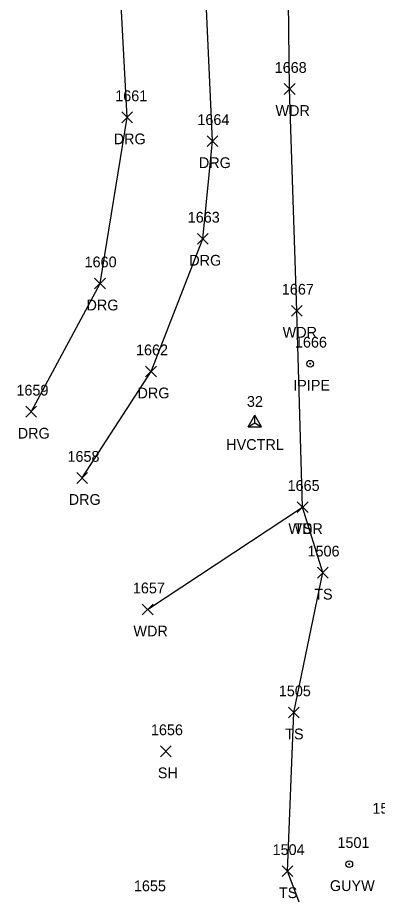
# Model space of a CAD drawing. Extents: x 1551995 to 1555700, y 777276 to 783130.
# Drawn here: x 1554729.2 to 1554796.1, y 777646.9 to 777809.8 of the extents above; entities that cross this region are included whole.
import ezdxf

# ---------------------------------------------------------------- set-up
doc = ezdxf.new("R2010")
doc.units = 0
for name, color, linetype in [('C_A', 7, 'Continuous'), ('C_I', 7, 'Continuous'), ('CPSM', 7, 'Continuous'), ('L_A', 7, 'Continuous'), ('L_I', 7, 'Continuous'), ('L_TIC', 7, 'Continuous'), ('LAWA', 7, 'Continuous'), ('LELB', 7, 'Continuous'), ('M_A', 7, 'Continuous'), ('M_I', 7, 'Continuous'), ('MPIP', 7, 'Continuous'), ('R_A', 7, 'Continuous'), ('R_I', 7, 'Continuous'), ('R_TIC', 7, 'Continuous'), ('RDG', 7, 'Continuous'), ('U_A', 7, 'Continuous'), ('U_I', 7, 'Continuous'), ('UPGW', 7, 'Continuous')]:
    doc.layers.add(name, color=color, linetype=linetype)

msp = doc.modelspace()

# ---------------------------------------------------------------- linework, layer by layer
at = {"layer": 'CPSM'}
for p, q in [((1554772.03, 777733.75), (1554773.28, 777735.92)), ((1554774.53, 777733.75), (1554773.28, 777735.92)), ((1554773.28, 777734.47), (1554773.28, 777735.92)), ((1554772.03, 777733.75), (1554773.28, 777734.47)), ((1554773.28, 777734.47), (1554773.28, 777734.47)), ((1554773.28, 777734.47), (1554774.53, 777733.75)), ((1554772.03, 777733.75), (1554774.53, 777733.75))]:
    msp.add_line(p, q, dxfattribs=at)
at = {"layer": 'L_TIC'}
for points in [[(1554778.76, 777795.52), (1554780.76, 777797.52)], [(1554780.76, 777795.52), (1554778.76, 777797.52)], [(1554780.09, 777754.32), (1554782.09, 777756.32)], [(1554782.09, 777754.32), (1554780.09, 777756.32)], [(1554781.17, 777717.85), (1554783.17, 777719.85)], [(1554783.17, 777717.85), (1554781.17, 777719.85)], [(1554781.17, 777717.85), (1554783.17, 777719.85)], [(1554783.17, 777717.85), (1554781.17, 777719.85)], [(1554784.91, 777705.67), (1554786.91, 777707.67)], [(1554786.91, 777705.67), (1554784.91, 777707.67)], [(1554752.38, 777698.82), (1554754.38, 777700.82)], [(1554754.38, 777698.82), (1554752.38, 777700.82)], [(1554779.53, 777679.7), (1554781.53, 777681.7)], [(1554781.53, 777679.7), (1554779.53, 777681.7)], [(1554755.78, 777672.47), (1554757.78, 777674.47)], [(1554757.78, 777672.47), (1554755.78, 777674.47)], [(1554778.36, 777650.21), (1554780.36, 777652.21)], [(1554780.36, 777650.21), (1554778.36, 777652.21)]]:
    msp.add_lwpolyline(points, dxfattribs=at)
at = {"layer": 'LAWA'}
msp.add_lwpolyline([(1554753.38, 777699.82), (1554782.17, 777718.85), (1554781.09, 777755.32), (1554779.76, 777796.52), (1554779.3, 777834.65), (1554766.43, 777889.19), (1554764.95, 777942.26), (1554753, 777988.87), (1554759.44, 778026.67), (1554773.64, 778068.32), (1554781.91, 778071.15), (1554798.07, 778075.08), (1554813.64, 778080.72)], dxfattribs=at)
at = {"layer": 'LELB'}
msp.add_lwpolyline([(1554784.41, 777637.79), (1554779.36, 777651.21), (1554780.53, 777680.7), (1554785.91, 777706.67), (1554782.17, 777718.85)], dxfattribs=at)
at = {"layer": 'MPIP'}
for radius in [0.625, 0.0833]:
    msp.add_circle((1554783.58, 777745.48), radius, dxfattribs=at)
at = {"layer": 'R_TIC'}
for points in [[(1554748.58, 777790.25), (1554750.58, 777792.25)], [(1554750.58, 777790.25), (1554748.58, 777792.25)], [(1554764.41, 777785.83), (1554766.41, 777787.83)], [(1554766.41, 777785.83), (1554764.41, 777787.83)], [(1554762.62, 777767.7), (1554764.62, 777769.7)], [(1554764.62, 777767.7), (1554762.62, 777769.7)], [(1554743.54, 777759.39), (1554745.54, 777761.39)], [(1554745.54, 777759.39), (1554743.54, 777761.39)], [(1554753.01, 777743.05), (1554755.01, 777745.05)], [(1554755.01, 777743.05), (1554753.01, 777745.05)], [(1554730.76, 777735.57), (1554732.76, 777737.57)], [(1554732.76, 777735.57), (1554730.76, 777737.57)], [(1554740.23, 777723.26), (1554742.23, 777725.26)], [(1554742.23, 777723.26), (1554740.23, 777725.26)]]:
    msp.add_lwpolyline(points, dxfattribs=at)
at = {"layer": 'RDG'}
for points in [[(1554731.76, 777736.57), (1554744.54, 777760.39), (1554749.58, 777791.25), (1554744.63, 777884.27), (1554742.18, 777937.77), (1554733.78, 777989.36), (1554731.62, 778029.74), (1554732.87, 778072.64), (1554738.87, 778112.72), (1554741.1, 778122.89), (1554752.14, 778165.58), (1554757.04, 778182.47), (1554765.14, 778213.69), (1554774.89, 778246.18), (1554785.77, 778269.3), (1554800.7, 778290.2), (1554833.81, 778326.22), (1554863.94, 778353.44), (1554894.55, 778381.82), (1554916.32, 778408.8)], [(1554741.23, 777724.26), (1554754.01, 777744.05), (1554763.62, 777768.7), (1554765.41, 777786.83), (1554760.87, 777887.93)]]:
    msp.add_lwpolyline(points, dxfattribs=at)
at = {"layer": 'UPGW'}
for radius in [0.625, 0.0833]:
    msp.add_circle((1554790.84, 777652.52), radius, dxfattribs=at)

# ---------------------------------------------------------------- texts
at = {"layer": 'C_A'}
msp.add_text('HVCTRL', height=2, dxfattribs=at).set_placement((1554767.98, 777729.47))
at = {"layer": 'C_I'}
msp.add_text('32', height=2, dxfattribs=at).set_placement((1554771.82, 777737.47))
at = {"layer": 'L_A'}
for s, p in [('WDR', (1554777.13, 777791.52)), ('WDR', (1554778.46, 777750.32)), ('WDR', (1554779.53, 777713.85)), ('TS', (1554780.58, 777713.85)), ('TS', (1554784.32, 777701.67)), ('WDR', (1554750.74, 777694.82)), ('TS', (1554778.93, 777675.7)), ('SH', (1554755.27, 777668.47)), ('TS', (1554777.77, 777646.21))]:
    msp.add_text(s, height=2, dxfattribs=at).set_placement(p)
at = {"layer": 'L_I'}
for s, p in [('1668', (1554776.98, 777799.52)), ('1667', (1554778.31, 777758.32)), ('1665', (1554779.38, 777721.85)), ('1665', (1554779.38, 777721.85)), ('1506', (1554783.08, 777709.67)), ('1657', (1554750.64, 777702.82)), ('1505', (1554777.75, 777683.7)), ('1656', (1554753.99, 777676.47)), ('1500', (1554795.14, 777661.89)), ('1504', (1554776.59, 777654.21)), ('1655', (1554750.83, 777647.48))]:
    msp.add_text(s, height=2, dxfattribs=at).set_placement(p)
at = {"layer": 'M_A'}
msp.add_text('IPIPE', height=2, dxfattribs=at).set_placement((1554780.42, 777740.48))
at = {"layer": 'M_I'}
msp.add_text('1666', height=2, dxfattribs=at).set_placement((1554780.74, 777748.48))
at = {"layer": 'R_A'}
for p in [(1554747.07, 777786.25), (1554762.9, 777781.83), (1554761.11, 777763.7), (1554742.03, 777755.39), (1554751.5, 777739.05), (1554729.25, 777731.57), (1554738.72, 777719.26)]:
    msp.add_text('DRG', height=2, dxfattribs=at).set_placement(p)
at = {"layer": 'R_I'}
for s, p in [('1661', (1554747.36, 777794.25)), ('1664', (1554762.62, 777789.83)), ('1663', (1554760.83, 777771.7)), ('1660', (1554741.67, 777763.39)), ('1662', (1554751.22, 777747.05)), ('1659', (1554729.01, 777739.57)), ('1658', (1554738.49, 777727.26))]:
    msp.add_text(s, height=2, dxfattribs=at).set_placement(p)
at = {"layer": 'U_A'}
msp.add_text('GUYW', height=2, dxfattribs=at).set_placement((1554787.24, 777647.52))
at = {"layer": 'U_I'}
msp.add_text('1501', height=2, dxfattribs=at).set_placement((1554788.64, 777655.52))

doc.saveas('drawing.dxf')
